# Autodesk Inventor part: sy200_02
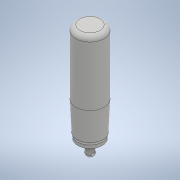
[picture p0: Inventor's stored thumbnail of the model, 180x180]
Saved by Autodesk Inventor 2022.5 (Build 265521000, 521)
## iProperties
Part Number: sy200_02
Material: 一般
Document SubType Name: Modeling
Designer: ImaoCorp
Density: 1 g/cm^3
Appearance: 既定
Author: ImaoCorp
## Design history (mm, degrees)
feature "sy200_02"
node "ソリッド1"
